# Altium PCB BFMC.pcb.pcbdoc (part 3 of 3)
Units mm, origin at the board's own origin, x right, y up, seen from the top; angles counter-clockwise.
Board outline 121.38 x 89.66 mm, 2 copper layers (Top Layer, Bottom Layer); 106 components, 51 nets, 277 pads, 97 vias.
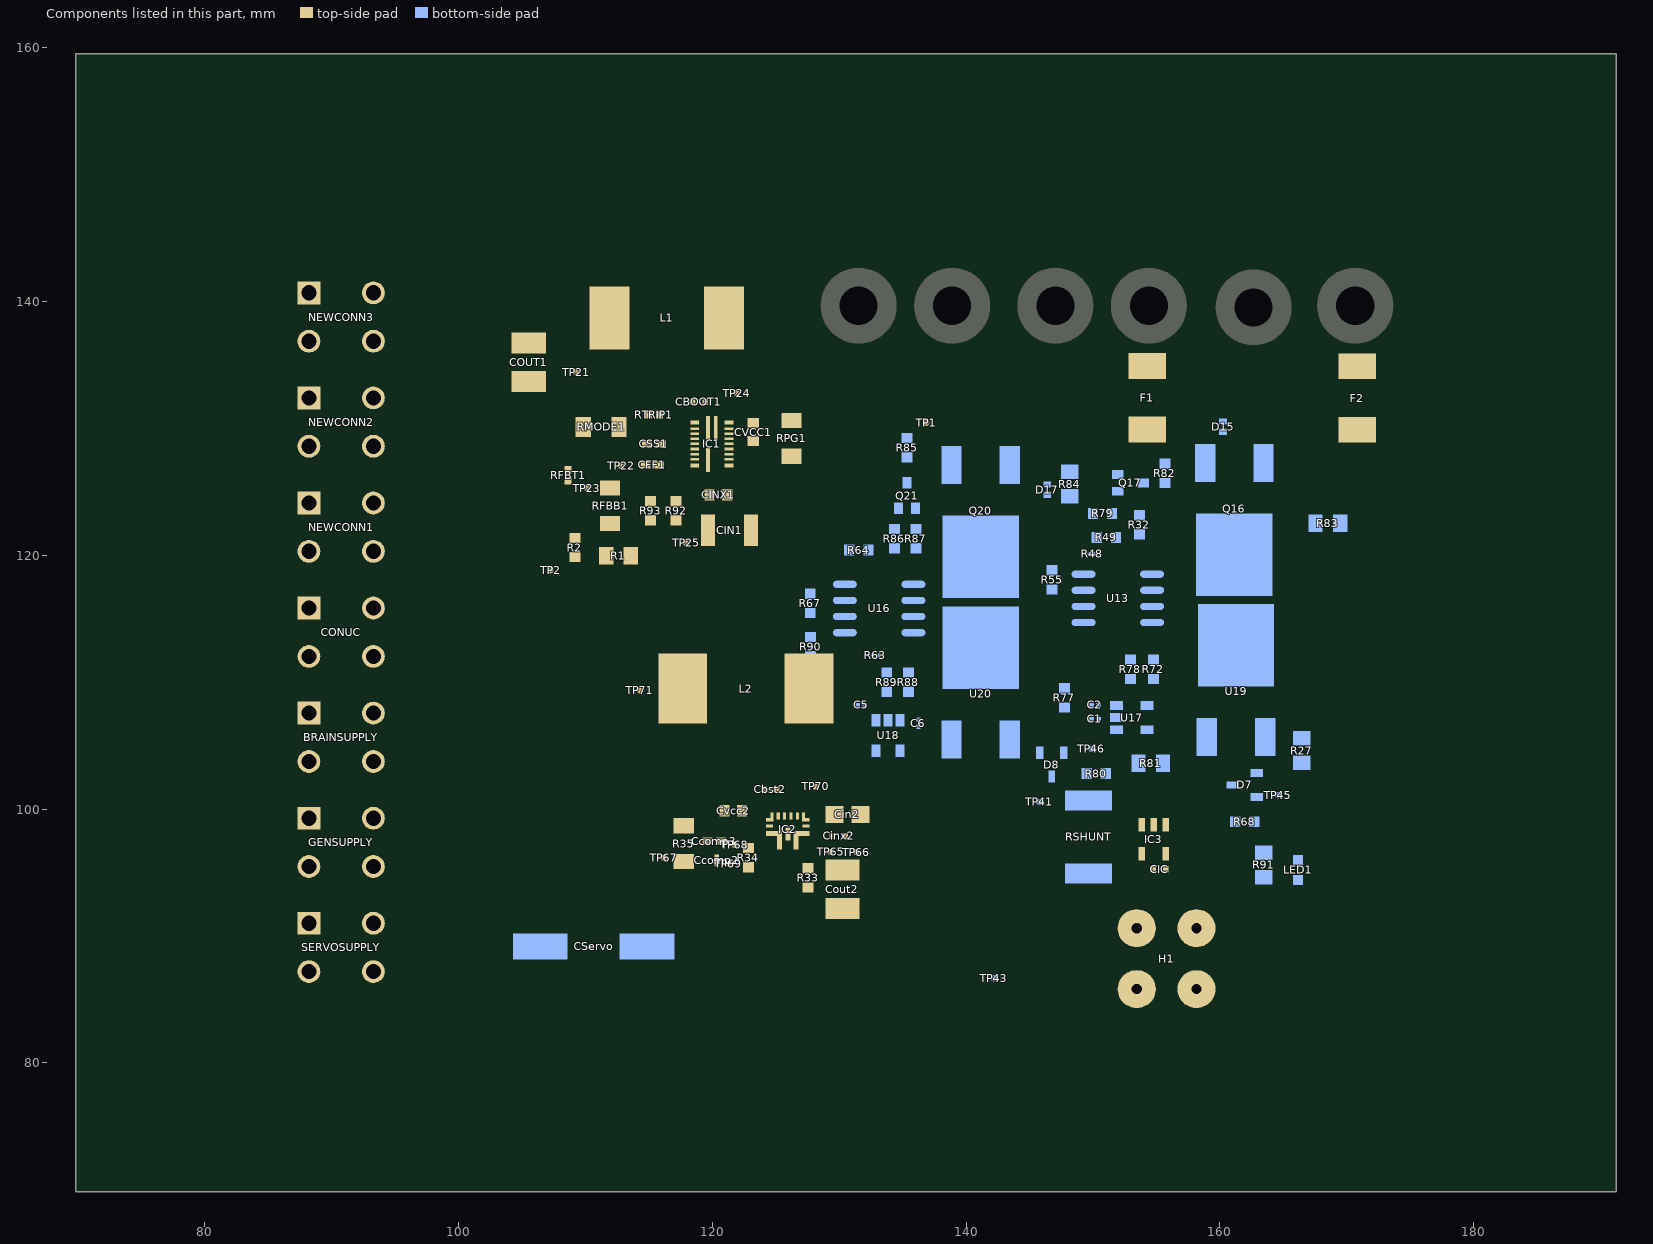
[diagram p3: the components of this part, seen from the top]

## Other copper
Top Layer:
  region net ISHUNT: 156.565,98.494 156.565,98.994 cw(c156.565,102.101) 155.995,99.046 155.995,98.441 cw(c156.565,95.386)
  region net UBATT: 152.813,99.002 152.813,98.502 cw(c152.813,97.395) 153.563,98.209 153.563,99.279 cw(c152.813,100.156)
  region net OUT_BATT: 152.813,96.724 152.813,96.224 cw(c152.813,90.864) 153.563,96.171 153.563,96.776 cw(c152.813,102.083)
  region net +5V: 155.47,95.256 155.97,95.256 cw(c165.333,95.256) 155.995,95.939 155.463,95.939 cw(c122.273,95.256)
  region net ADC1: 110.068,119.684 110.068,119.984 cw(c110.068,120.546) 109.618,120.209 109.618,119.459 cw(c110.068,119.121)
  region net ADC1: 108.304,119.984 108.304,119.684 cw(c108.304,119.121) 108.754,119.459 108.754,120.209 cw(c108.304,120.546)
  region net ADC1: 107.614,118.952 107.402,119.164 107.351,119.114 107.334,119.1 107.316,119.087 107.297,119.078 107.275,119.071 107.252,119.067 107.517,118.802 107.52,118.825 107.527,118.847 107.537,118.866 107.55,118.884 107.564,118.902
  region net VOUT1: 126.458,96.593 126.758,96.593 cw(c127.322,96.593) 126.808,96.825 126.408,96.825 cw(c125.895,96.593)
  region: 125.181,96.444 125.435,96.444 cw(c128.158,96.444) 125.462,96.825 125.155,96.825 cw(c122.459,96.444)
  region net VOUT1: 128.024,97.948 128.024,98.202 cw(c128.024,100.715) 127.658,98.228 127.658,97.921 cw(c128.024,95.434)
  region net SW_1: 126.108,98.775 125.808,98.775 cw(c124.805,98.775) 125.777,98.525 126.14,98.525 cw(c127.112,98.775)
  region: 124.162,98.202 124.162,97.948 cw(c124.162,97.761) 124.258,97.921 124.258,98.228 cw(c124.162,98.388)
  region: 125.458,98.656 125.204,98.656 cw(c124.728,98.656) 125.014,98.275 125.485,98.275 cw(c128.181,98.656)
  region net $3N2936: 120.97,95.55 120.97,95.85 cw(c120.97,98.827) 120.52,95.885 120.52,95.516 cw(c120.97,92.574)
  region net COMP: 121.899,96.822 122.111,97.034 122.08,97.066 122.066,97.083 122.053,97.101 122.041,97.12 122.032,97.139 122.026,97.16 122.023,97.181 121.758,96.916 121.78,96.913 121.801,96.906 121.819,96.897 121.835,96.885 121.851,96.871
  region net COMP: 121.636,97.509 121.424,97.297 121.476,97.247 121.49,97.231 121.503,97.214 121.513,97.195 121.52,97.174 121.524,97.15 121.789,97.415 121.766,97.418 121.745,97.425 121.725,97.435 121.706,97.447 121.687,97.461 121.653,97.493
  region net $3N2936: 121.57,95.541 121.57,95.841 121.535,95.842 121.517,95.844 121.499,95.848 121.481,95.853 121.465,95.859 121.45,95.868 121.436,95.878 121.436,95.503 121.45,95.513 121.465,95.522 121.481,95.528 121.499,95.533 121.517,95.537 121.535,95.539
  region net $3N2936: 120.93,95.85 120.93,95.55 120.977,95.549 121,95.546 121.023,95.542 121.046,95.536 121.067,95.527 121.087,95.517 121.105,95.503 121.105,95.878 121.085,95.863 121.065,95.854 121.045,95.848 121.024,95.846 121.003,95.847
  region net FB: 115.673,126.467 115.973,126.467 cw(c116.391,126.467) 116.198,126.838 115.448,126.838 cw(c115.254,126.467)
  region net FB: 116.518,127.008 116.518,127.208 cw(c116.518,127.583) 116.218,127.358 116.218,126.858 cw(c116.518,126.633)
  region net SS_REFIN: 116.645,128.659 116.645,128.859 cw(c116.645,129.234) 116.345,129.009 116.345,128.509 cw(c116.645,128.284)
  region net BOOT: 118.022,130.609 118.022,130.309 ccw(c118.022,130.859) 118.276,130.371 118.276,130.547 ccw(c118.022,130.058)
  region: 117.976,130.059 117.976,129.859 cw(c117.976,-124.034) 118.276,129.858 118.276,129.859 118.276,130.059 118.276,130.058 ccw(c117.976,-123.834)
  region net TRIP: 117.976,129.659 117.976,129.459 cw(c117.976,-124.434) 118.276,129.458 118.276,129.459 118.276,129.659 118.276,129.658 ccw(c117.976,-124.234)
  region net MODE: 117.976,129.259 117.976,129.059 cw(c117.976,-124.834) 118.276,129.058 118.276,129.059 118.276,129.259 118.276,129.258 ccw(c117.976,-124.634)
  region net SS_REFIN: 117.976,128.859 117.976,128.659 ccw(c117.976,129.766) 118.276,128.7 118.276,128.817 ccw(c117.976,127.751)
  region: 117.976,128.459 117.976,128.259 ccw(c117.976,129.366) 118.276,128.3 118.276,128.417 ccw(c117.976,127.351)
  region net FB: 117.976,128.059 117.976,127.859 cw(c117.976,-126.034) 118.276,127.858 118.276,127.859 118.276,128.059 118.276,128.058 ccw(c117.976,-125.834)
  region net EN: 117.976,127.659 117.976,127.459 cw(c117.976,-126.434) 118.276,127.458 118.276,127.459 118.276,127.659 118.276,127.658 ccw(c117.976,-126.234)
  region net PGOOD: 118.198,127.209 118.198,126.909 ccw(c118.198,126.989) 118.276,126.971 118.276,127.147 ccw(c118.198,127.129)
  region net VCC: 122.126,130.309 122.126,130.609 ccw(c122.126,128.947) 121.676,130.547 121.676,130.371 ccw(c122.126,131.97)
  region: 121.176,129.559 121.476,129.559 cw(c122.914,129.559) 121.508,129.859 121.145,129.859 cw(c119.738,129.559)
  region: 121.176,129.159 121.476,129.159 cw(c122.914,129.159) 121.508,129.459 121.145,129.459 cw(c119.738,129.159)
  region: 121.476,129.959 121.176,129.959 cw(c120.851,129.959) 120.976,129.659 121.676,129.659 cw(c121.801,129.959)
  region: 121.176,128.759 121.476,128.759 cw(c122.914,128.759) 121.508,129.059 121.145,129.059 cw(c119.738,128.759)
  region: 121.476,129.559 121.176,129.559 cw(c120.851,129.559) 120.976,129.259 121.676,129.259 cw(c121.801,129.559)
  region: 121.176,128.359 121.476,128.359 cw(c122.914,128.359) 121.508,128.659 121.145,128.659 cw(c119.738,128.359)
  region: 121.476,129.159 121.176,129.159 cw(c120.851,129.159) 120.976,128.859 121.676,128.859 cw(c121.801,129.159)
  region: 121.476,128.759 121.176,128.759 cw(c120.851,128.759) 120.976,128.459 121.676,128.459 cw(c121.801,128.759)
  region: 121.176,127.959 121.476,127.959 cw(c122.914,127.959) 121.508,128.259 121.145,128.259 cw(c119.738,127.959)
  region: 121.176,127.559 121.476,127.559 cw(c122.914,127.559) 121.508,127.859 121.145,127.859 cw(c119.738,127.559)
  region: 121.476,128.359 121.176,128.359 cw(c120.851,128.359) 120.976,128.059 121.676,128.059 cw(c121.801,128.359)
  region: 121.176,127.059 121.476,127.059 cw(c124.021,127.059) 121.508,127.459 121.145,127.459 cw(c118.632,127.059)
  region: 121.476,127.959 121.176,127.959 cw(c120.851,127.959) 120.976,127.659 121.676,127.659 cw(c121.801,127.959)
  region: 121.476,127.559 121.176,127.559 cw(c120.77,127.559) 120.976,127.209 121.676,127.209 cw(c121.883,127.559)
  region: 122.057,126.932 122.057,127.186 cw(c122.057,130.522) 121.676,127.207 121.676,126.91 cw(c122.057,123.596)
  region net SW: 120.403,131.34 120.149,131.34 cw(c116.813,131.34) 120.128,130.959 120.425,130.959 cw(c123.739,131.34)
  region net FB: 109.851,125.446 109.851,125.146 109.87,125.144 109.886,125.14 109.901,125.133 109.915,125.124 109.928,125.114 109.969,125.077 109.969,125.452 109.954,125.441 109.941,125.436 109.928,125.434 109.915,125.435 109.887,125.442 109.871,125.444
  region net FB: 110.475,125.146 110.475,125.446 110.46,125.445 110.446,125.444 110.433,125.441 110.41,125.436 110.379,125.428 110.37,125.426 110.361,125.426 110.351,125.426 110.342,125.428 110.332,125.431 110.322,125.436 110.311,125.443 110.3,125.452 110.3,125.077 110.316,125.09 110.336,125.102 110.359,125.114 110.382,125.124 110.407,125.133 110.431,125.14 110.454,125.144
  region net VBATT1: 152.046,87.564 151.693,87.21 151.783,87.115 151.847,87.041 151.896,86.976 151.942,86.91 151.974,86.856 152.003,86.801 152.022,86.76 152.038,86.717 152.051,86.674 152.062,86.631 152.067,86.602 152.071,86.573 152.073,86.543 152.073,86.514 152.072,86.484 152.069,86.454 152.064,86.424 152.058,86.394 152.05,86.363 152.039,86.333 152.923,87.217 152.893,87.206 152.862,87.198 152.832,87.192 152.802,87.187 152.772,87.184 152.743,87.183 152.713,87.183 152.683,87.186 152.654,87.189 152.611,87.197 152.567,87.209 152.525,87.223 152.483,87.24 152.441,87.26 152.386,87.289 152.332,87.323 152.267,87.369 152.19,87.43 152.105,87.507
  region net OUT_BATT2: 158.545,93.256 157.745,93.256 157.743,93.161 157.732,93.037 157.713,92.908 157.687,92.776 157.653,92.642 157.612,92.509 157.564,92.379 157.509,92.251 157.448,92.13 157.395,92.037 157.338,91.95 157.293,91.888 157.246,91.831 157.196,91.778 157.145,91.729 159.145,91.729 159.094,91.778 159.045,91.831 158.998,91.888 158.938,91.971 158.882,92.06 158.83,92.153 158.77,92.276 158.717,92.404 158.67,92.536 158.631,92.669 158.598,92.802 158.573,92.934 158.556,93.062 158.547,93.185
  region net EN: 116.338,124.376 116.338,124.122 cw(c116.338,123.646) 116.719,123.932 116.719,124.567 cw(c116.338,124.852)
  region net EN: 115.964,124.122 115.964,124.376 cw(c115.964,124.852) 115.583,124.567 115.583,123.932 cw(c115.964,123.646)
  region net VOUT1: 132.177,94.692 132.177,95.692 cw(c132.177,96.36) 131.608,96.01 131.608,94.375 cw(c132.177,94.024)
  region net COMP: 121.458,97.325 121.458,97.625 cw(c121.458,99.687) 121.099,97.656 121.099,97.293 cw(c121.458,95.262)
  region net FB_1: 119.009,98.525 119.009,98.825 cw(c119.009,99.387) 118.559,99.05 118.559,98.3 cw(c119.009,97.962)
  region net FB_1: 126.376,94.071 126.376,93.571 cw(c126.376,88.212) 127.126,93.519 127.126,94.124 cw(c126.376,99.431)
  region net COMP: 122.005,97.078 122.005,96.778 cw(c122.005,96.271) 122.426,96.553 122.426,97.303 cw(c122.005,97.585)
  region net COMP: 123.029,97.712 122.775,97.712 cw(c122.299,97.712) 122.585,97.331 123.22,97.331 cw(c123.506,97.712)
  region net $3N2936: 121.976,95.571 121.976,95.271 cw(c121.976,94.709) 122.426,95.046 122.426,95.796 cw(c121.976,96.134)
  region net MODE: 113.551,129.802 113.551,130.002 cw(c113.551,130.377) 113.251,130.152 113.251,129.652 cw(c113.551,129.427)
  region net VCC: 124.152,130.246 124.152,130.546 cw(c124.152,131.108) 123.702,130.771 123.702,130.021 cw(c124.152,129.683)
  region net VCC: 122.352,130.609 122.352,130.309 cw(c122.352,129.746) 122.802,130.084 122.802,130.796 cw(c122.352,131.243)
  region net FB: 109.351,125.646 109.351,125.946 cw(c109.351,126.508) 108.921,126.146 108.921,125.58 cw(c109.351,124.204)
  region net FB: 113.202,125.146 113.202,125.446 cw(c113.202,126.008) 112.752,125.671 112.752,124.921 cw(c113.202,124.583)
  region net FB: 110.701,125.446 110.701,125.146 cw(c110.701,124.583) 111.151,124.921 111.151,125.671 cw(c110.701,126.008)
  region net VCC: 125.001,130.546 125.001,130.246 cw(c125.001,129.683) 125.451,130.021 125.451,130.771 cw(c125.001,131.108)
  region net PGOOD: 126.101,126.746 126.401,126.746 cw(c126.964,126.746) 126.626,127.196 125.876,127.196 cw(c125.539,126.746)
  region net SW_1: 123.383,101.725 123.383,101.425 cw(c123.383,100.362) 123.833,101.325 123.833,101.825 cw(c123.383,102.787)
  region net BOOT: 118.027,132.246 118.027,131.946 cw(c118.027,131.697) 118.226,131.846 118.226,132.346 cw(c118.027,132.494)
  region net OUT_BATT: 114.598,119.811 114.598,120.111 cw(c114.598,120.673) 114.148,120.336 114.148,119.586 cw(c114.598,119.248)
  region net ADC1: 110.633,119.984 110.633,119.684 cw(c110.633,119.121) 111.083,119.459 111.083,120.209 cw(c110.633,120.546)
  region net ADC1: 94.537,115.581 94.537,116.081 94.493,116.083 94.453,116.087 94.427,116.091 94.403,116.096 94.38,116.102 94.358,116.109 94.337,116.118 94.316,116.127 94.297,116.137 94.269,116.154 94.242,116.172 94.216,116.192 94.183,116.221 94.135,116.27 93.999,116.417 93.94,116.476 93.907,116.506 93.907,115.156 93.97,115.216 94.095,115.349 94.167,115.425 94.2,115.456 94.225,115.477 94.251,115.497 94.278,115.514 94.306,115.531 94.326,115.54 94.347,115.549 94.369,115.557 94.391,115.563 94.415,115.569 94.44,115.574 94.479,115.579 94.522,115.581
  region: 117.24,128.167 117.098,128.308 117.08,128.292 117.059,128.279 117.037,128.269 117.013,128.261 116.988,128.255 116.963,128.251 116.913,128.246 117.178,127.981 117.183,128.031 117.187,128.056 117.193,128.081 117.201,128.105 117.211,128.127 117.224,128.148
  region: 117.136,130.644 117.277,130.785 117.268,130.797 117.262,130.81 117.259,130.825 117.258,130.841 117.259,130.858 117.262,130.876 117.271,130.914 117.295,130.991 117.299,131.01 117.303,131.028 117.305,131.044 117.305,131.06 117.04,130.795 117.058,130.789 117.072,130.775 117.084,130.756 117.094,130.733 117.112,130.683 117.123,130.661
  region net PGOOD: 118.094,126.436 117.794,126.436 117.797,126.375 117.797,126.353 117.797,126.342 117.796,126.331 117.794,126.321 117.792,126.311 117.788,126.301 117.784,126.291 117.779,126.281 117.772,126.271 117.764,126.261 118.139,126.261 118.125,126.279 118.115,126.299 118.107,126.32 118.101,126.343 118.098,126.366 118.095,126.413
  region net PGOOD: 125.998,126.23 125.786,126.442 125.735,126.392 125.718,126.378 125.7,126.365 125.681,126.356 125.659,126.349 125.636,126.345 125.901,126.08 125.904,126.104 125.911,126.125 125.921,126.144 125.934,126.162 125.948,126.18
  region net FB: 109.851,125.446 109.851,125.146 109.87,125.144 109.886,125.14 109.901,125.133 109.915,125.124 109.928,125.114 109.969,125.077 109.969,125.452 109.954,125.441 109.941,125.436 109.928,125.434 109.915,125.435 109.887,125.442 109.871,125.444
  region net FB: 110.475,125.146 110.475,125.446 110.46,125.445 110.446,125.444 110.433,125.441 110.41,125.436 110.379,125.428 110.37,125.426 110.361,125.426 110.351,125.426 110.342,125.428 110.332,125.431 110.322,125.436 110.311,125.443 110.3,125.452 110.3,125.077 110.316,125.09 110.336,125.102 110.359,125.114 110.382,125.124 110.407,125.133 110.431,125.14 110.454,125.144
  region net COMP: 121.899,96.822 122.111,97.034 122.08,97.066 122.066,97.083 122.053,97.101 122.041,97.12 122.032,97.139 122.026,97.16 122.023,97.181 121.758,96.916 121.78,96.913 121.801,96.906 121.819,96.897 121.835,96.885 121.851,96.871
  region net COMP: 121.636,97.509 121.424,97.297 121.476,97.247 121.49,97.231 121.503,97.214 121.513,97.195 121.52,97.174 121.524,97.15 121.789,97.415 121.766,97.418 121.745,97.425 121.725,97.435 121.706,97.447 121.687,97.461 121.653,97.493
  region net ADC1: 110.068,119.684 110.068,119.984 cw(c110.068,120.546) 109.618,120.209 109.618,119.459 cw(c110.068,119.121)
  region net ADC1: 108.304,119.984 108.304,119.684 cw(c108.304,119.121) 108.754,119.459 108.754,120.209 cw(c108.304,120.546)
  region net VOUT1: 132.562,93.164 133.562,93.164 133.062,93.807 132.531,95.546
Bottom Layer:
  region net VBATT1: 150.901,107.246 150.901,106.946 cw(c150.877,106.884) 150.931,106.922 150.931,107.266 cw(c150.838,107.369)
  region net VBATT1: 150.931,107.266 150.931,107.471 cw(c150.838,107.369)
  region net VBATT1: 150.931,106.922 cw(c150.877,106.884) 150.931,106.846
  region: 150.004,107.639 149.75,107.639 cw(c147.027,107.639) 149.723,107.258 150.031,107.258 cw(c152.727,107.639)
  region net VBATT1: 151.06,106.946 151.06,107.246 ccw(c151.06,105.584) 150.61,107.184 150.61,107.008 ccw(c151.06,108.607)
  region: 149.75,107.653 150.004,107.653 cw(c151.301,107.653) 150.061,108.034 149.693,108.034 cw(c148.453,107.653)
  region net +VCC2: 151.06,108.046 151.06,108.346 ccw(c151.06,106.684) 150.61,108.284 150.61,108.108 ccw(c151.06,109.707)
  region net $1N1798: 163.766,102.596 163.766,103.096 cw(c163.766,104.508) 163.376,103.151 163.376,102.541 cw(c163.766,101.183)
  region net $1N1798: 163.139,103.432 162.639,103.432 cw(c161.861,103.432) 162.586,103.151 163.191,103.151 cw(c163.916,103.432)
  region net UBATT: 159.777,102.146 159.777,101.646 ccw(c159.777,104.414) 160.527,101.749 160.527,102.042 ccw(c159.777,99.377)
  region net $1N1788: 145.951,104.974 145.651,104.974 cw(c145.591,104.974) 145.62,104.921 145.983,104.921 cw(c146.012,104.974)
  region net $1N1788: 146.102,104.974 145.502,104.974 ccw(c145.575,104.974) 145.626,104.921 145.977,104.921 ccw(c146.028,104.974)
  region net $1N2516: 151.685,124.38 152.185,124.38 cw(c153.097,124.38) 152.238,124.685 151.633,124.685 cw(c150.774,124.38)
  region net $1N2412: 155.167,125.446 155.167,125.946 cw(c155.167,131.305) 154.417,125.998 154.417,125.393 cw(c155.167,120.086)
  region net $1N20962: 152.751,121.146 152.751,121.646 cw(c152.751,124.472) 152.208,121.698 152.208,121.093 cw(c152.751,118.32)
  region net $1N20946: 150.043,120.514 150.343,120.514 cw(c150.906,120.514) 150.568,120.964 150.011,120.964 cw(c146.827,120.514)
  region net $1N2337: 159.19,129.971 159.19,129.471 ccw(c159.19,132.239) 159.94,129.574 159.94,129.867 ccw(c159.19,127.202)
  region net $1N20674: 146.501,116.149 147.001,116.149 cw(c152.361,116.149) 147.054,116.899 146.449,116.899 cw(c141.142,116.149)
  region net $1N20674: 147.96,116.981 147.96,117.481 cw(c147.96,118.844) 147.21,117.706 147.21,116.899 cw(c147.96,113.494)
  region net VBATT2: 132.176,108.808 131.876,108.808 cw(c128.899,108.808) 131.842,108.358 132.21,108.358 cw(c135.152,108.808)
  region net VBATT2: 132.66,108.046 132.66,108.346 cw(c132.66,116.788) 132.21,108.358 132.21,108.034 cw(c132.66,99.603)
  region net +VCC3: 135.625,107.146 135.625,106.846 cw(c135.625,71.97) 136.075,106.843 136.075,107.211 cw(c135.625,108.724)
  region net +VCC3: 136.387,107.661 136.087,107.661 ccw(c137.749,107.661) 136.15,107.211 136.325,107.211 ccw(c134.726,107.661)
  region net $1N27792: 140.137,126.86 140.137,127.36 cw(c140.137,127.861) 139.652,127.735 139.652,126.485 cw(c140.137,126.358)
  region net $1N27792: 139.102,129.36 138.602,129.36 cw(c137.665,129.36) 138.227,128.61 139.477,128.61 cw(c140.04,129.36)
  region net $1N27799: 135.801,122.48 136.301,122.48 cw(c141.661,122.48) 136.354,123.23 135.749,123.23 cw(c130.442,122.48)
  region net $1N27793: 135.601,126.912 135.101,126.912 cw(c129.742,126.912) 135.049,126.162 135.654,126.162 cw(c140.961,126.912)
  region net $1N27811: 133.458,120.146 133.458,120.646 cw(c133.458,126.005) 132.708,120.698 132.708,120.093 cw(c133.458,114.786)
  region net $1N27807: 131.407,119.433 131.732,119.816 cw(c136.071,124.154) 131.201,120.421 130.802,119.964 cw(c127.068,115.094)
  region net $1N27822: 128.37,115.192 128.37,115.692 cw(c128.37,116.151) 128.156,115.745 128.156,115.14 cw(c128.37,114.733)
  region net $1N27822: 127.501,114.289 128.001,114.289 cw(c129.893,114.289) 128.156,115.039 127.292,115.039 cw(c126.051,114.289)
  region net VBATT1: 147.501,106.851 148.001,106.851 cw(c149.638,106.851) 148.183,107.601 147.319,107.601 cw(c145.865,106.851)
  region net $1N20674: 148.001,110.606 147.501,110.606 cw(c146.097,110.606) 147.319,109.914 148.183,109.914 cw(c149.406,110.606)
  region net +VCC2: 152.701,109.246 153.201,109.246 cw(c154.26,109.246) 153.383,109.839 152.519,109.839 cw(c151.643,109.246)
  region net +VCC2: 151.985,110.432 151.985,109.932 cw(c151.985,108.345) 152.519,109.839 152.519,110.646 cw(c151.985,111.205)
  region net $1N21052: 154.133,111.499 154.133,111.999 cw(c154.133,117.359) 153.383,112.052 153.383,111.446 cw(c154.133,106.139)
  region net $1N21052: 153.569,111.999 153.569,111.499 cw(c153.569,109.587) 154.319,111.346 154.319,112.152 cw(c153.569,113.911)
  region net $1N21052: 155.714,112.358 155.331,112.683 cw(c150.993,117.021) 154.727,112.152 155.183,111.753 cw(c160.053,108.019)
  region net $1N2516: 151.755,123.949 151.255,123.949 cw(c151.018,123.949) 151.102,123.728 151.908,123.728 cw(c151.991,123.949)
  region net $1N2516: 152.658,123.046 152.658,123.546 cw(c152.658,125.182) 151.908,123.728 151.908,122.864 cw(c152.658,121.409)
  region net UBATT: 160.948,97.814 161.448,97.814 cw(c163.36,97.814) 161.601,98.564 160.795,98.564 cw(c159.036,97.814)
  region net UBATT: 160.045,99.246 160.045,98.746 cw(c160.045,93.386) 160.795,98.693 160.795,99.298 cw(c160.045,104.605)
  region net $1N1798: 163.858,98.746 163.858,99.246 cw(c163.858,104.605) 163.108,99.298 163.108,98.693 cw(c163.858,93.386)
  region net $1N1788: 151.838,102.546 151.838,103.046 cw(c151.838,104.828) 151.408,103.098 151.408,102.493 cw(c151.838,100.763)
  region net $1N1788: 151.155,103.669 150.855,103.669 cw(c150.309,103.669) 150.63,103.228 151.38,103.228 cw(c151.701,103.669)
  region net $1N1798: 164.563,106.068 164.563,105.268 cw(c164.563,96.693) 165.763,105.184 165.763,105.903 ccw(c164.563,101.638)
  region net $1N1788: 152.638,103.846 152.638,103.346 cw(c152.638,102.965) 153.019,102.971 153.019,104.221 cw(c152.638,104.226)
  region net $1N2412: 154.486,125.946 154.486,125.446 cw(c154.486,123.655) 155.236,125.281 155.236,126.088 cw(c154.486,127.999)
  region net OUT_BATT1: 168.959,120.312 169.959,120.312 ccw(c164.421,120.312) 169.751,121.812 169.166,121.812 ccw(c174.496,120.312)
  region net OUT_BATT1: 169.918,124.389 169.118,124.389 cw(c160.542,124.389) 169.033,123.189 170.002,123.189 cw(c178.493,124.389)
  region net $1N2337: 167.835,123.665 167.335,123.665 cw(c166.843,123.665) 166.97,123.189 167.888,123.189 cw(c170.007,123.665)
  region net $1N27792: 146.713,124.956 146.713,124.456 cw(c146.713,123.518) 147.463,124.081 147.463,125.196 cw(c146.713,126.247)
  region net $1N27792: 135.598,129.875 135.098,129.875 cw(c134.838,129.875) 134.916,129.626 135.78,129.626 cw(c135.859,129.875)
  region net $1N27793: 135.101,126.563 135.601,126.563 cw(c137.262,126.563) 135.78,127.313 134.916,127.313 cw(c133.489,126.563)
  region net $1N27799: 134.869,122.299 134.869,121.799 cw(c134.869,116.439) 135.619,121.746 135.619,122.352 cw(c134.869,127.659)
  region net $1N27799: 136.301,123.202 135.801,123.202 cw(c134.165,123.202) 135.619,122.452 136.483,122.452 cw(c137.938,123.202)
  region net $1N32332: 134.942,109.964 134.701,109.78 cw(c133.906,108.985) 135.019,109.144 135.579,109.646 cw(c135.738,110.759)
  region net +VCC3: 136.237,110.667 136.237,110.967 cw(c136.237,111.397) 135.883,111.152 135.883,110.442 cw(c136.237,110.276)
  region net +VCC3: 135.701,111.809 135.201,111.809 cw(c133.927,111.809) 135.019,111.152 135.883,111.152 cw(c136.976,111.809)
  region net $1N32332: 134.454,110.028 134.502,110.404 cw(c137.105,113.008) 134.183,110.767 133.818,110.346 cw(c133.659,109.232)
  region net $1N27822: 128.001,114.702 127.501,114.702 cw(c122.142,114.702) 127.449,113.952 128.054,113.952 cw(c133.361,114.702)
  region net VBATT2: 127.351,110.439 128.151,110.439 ccw(c123.721,110.439) 127.986,111.639 127.517,111.639 ccw(c131.781,110.439)
  region net VBATT2: 128.633,111.892 128.633,112.192 cw(c128.633,112.755) 128.183,112.417 128.183,111.667 cw(c128.633,111.33)
  region net $1N1788: 150.036,104.426 150.248,104.638 150.237,104.648 150.226,104.657 150.215,104.665 150.195,104.677 150.168,104.692 150.16,104.698 150.153,104.704 150.146,104.71 150.141,104.718 150.136,104.727 150.132,104.738 150.13,104.751 150.128,104.765 149.863,104.5 149.884,104.498 149.907,104.492 149.931,104.485 149.955,104.476 149.979,104.465 150.001,104.453 150.02,104.44
  region net $1N1788: 149.767,105.119 149.555,104.907 149.569,104.891 149.582,104.872 149.594,104.85 149.605,104.826 149.614,104.802 149.621,104.778 149.626,104.755 149.629,104.734 149.894,104.999 149.879,105.001 149.867,105.003 149.856,105.007 149.847,105.012 149.839,105.017 149.833,105.024 149.827,105.031 149.821,105.039 149.806,105.066 149.794,105.086 149.786,105.097 149.777,105.108
  region net VBATT1: 150.901,107.246 150.901,106.946 cw(c150.901,105.883) 151.351,106.846 151.351,107.471 cw(c150.901,107.808)
  region net +VCC2: 150.901,108.346 150.901,108.046 cw(c150.901,107.483) 151.351,107.821 151.351,108.496 cw(c150.901,109.096)
  region net +VCC2: 152.882,108.822 152.378,109.026 cw(c148.039,113.365) 151.773,108.496 152.351,108.217 cw(c157.221,104.484)
  region net +VCC3: 135.601,106.846 135.601,107.146 cw(c135.601,107.708) 135.151,107.371 135.151,106.621 cw(c135.601,106.283)
  region net UBATT: 162.013,96.846 162.013,96.346 cw(c162.013,90.986) 162.763,96.293 162.763,96.898 cw(c162.013,102.205)
  region net $1N40141: 164.89,94.146 164.89,94.646 cw(c164.89,95.584) 164.14,95.021 164.14,94.093 cw(c164.89,88.786)
  region net $1N40141: 164.998,94.646 164.998,94.146 cw(c164.998,92.196) 165.748,93.996 165.748,94.796 cw(c164.998,96.596)
  region net $1N20931: 149.502,115.728 149.002,115.728 148.999,115.485 148.991,115.388 148.983,115.326 148.974,115.281 148.964,115.239 148.951,115.199 148.941,115.174 148.93,115.15 148.918,115.127 148.904,115.106 148.889,115.086 148.872,115.067 148.854,115.05 148.834,115.035 148.813,115.021 148.789,115.009 148.764,114.999 148.738,114.991 148.709,114.984 148.678,114.98 148.645,114.978 148.627,114.978 149.877,114.978 149.843,114.979 149.811,114.982 149.782,114.987 149.754,114.994 149.728,115.004 149.704,115.015 149.681,115.028 149.661,115.042 149.642,115.058 149.624,115.076 149.608,115.095 149.594,115.116 149.581,115.138 149.569,115.162 149.559,115.186 149.549,115.212 149.537,115.253 149.528,115.296 149.518,115.356 149.509,115.436 149.504,115.57
  region net $1N20931: 149.002,114.924 149.502,114.924 149.506,115.166 149.514,115.264 149.522,115.326 149.531,115.37 149.541,115.412 149.554,115.452 149.564,115.478 149.575,115.502 149.587,115.524 149.601,115.546 149.616,115.566 149.633,115.584 149.651,115.601 149.671,115.617 149.692,115.63 149.715,115.642 149.74,115.652 149.767,115.661 149.796,115.667 149.827,115.671 149.86,115.673 149.877,115.674 148.627,115.674 148.662,115.673 148.693,115.669 148.723,115.664 148.751,115.657 148.777,115.648 148.801,115.637 148.824,115.624 148.844,115.609 148.863,115.593 148.881,115.575 148.896,115.556 148.911,115.535 148.924,115.513 148.936,115.49 148.946,115.465 148.956,115.439 148.968,115.399 148.977,115.356 148.987,115.295 148.995,115.215 149.001,115.081
  region net $1N20931: 150.604,115.811 150.604,116.111 150.568,116.117 149.921,116.246 149.909,116.248 149.909,115.674 149.946,115.68 150.592,115.809
  region net $1N20674: 147.705,117.481 147.705,116.981 147.722,116.981 147.74,116.983 147.779,116.991 147.822,117.003 147.938,117.044 148.106,117.105 148.152,117.118 148.195,117.127 148.215,117.13 148.235,117.132 148.253,117.132 148.271,117.131 148.287,117.128 148.302,117.123 148.316,117.117 148.329,117.108 148.339,117.097 148.349,117.084 148.349,117.377 148.339,117.364 148.329,117.353 148.316,117.345 148.302,117.338 148.287,117.333 148.271,117.33 148.253,117.329 148.235,117.329 148.215,117.331 148.174,117.338 148.129,117.349 148.059,117.372 147.867,117.443 147.8,117.464 147.759,117.474 147.74,117.478 147.722,117.48
  region net +VCC2: 153.103,114.941 153.103,114.441 153.993,114.404 153.993,114.978
  region net $1N20962: 153.46,116.111 153.46,115.811 153.486,115.812 153.511,115.814 153.545,115.819 153.617,115.833 153.635,115.836 153.653,115.838 153.662,115.838 153.671,115.838 153.679,115.837 153.688,115.835 153.696,115.833 153.705,115.83 153.713,115.827 153.721,115.823 153.73,115.818 153.738,115.812 153.746,115.805 153.754,115.798 153.763,115.789 153.771,115.779 153.771,116.142 153.754,116.124 153.738,116.109 153.721,116.098 153.705,116.091 153.688,116.086 153.671,116.084 153.653,116.084 153.635,116.085 153.598,116.092 153.534,116.104 153.486,116.11
  region net $1N21052: 156.198,116.981 156.198,117.481 155.307,117.518 155.307,116.944
  region net $1N20946: 153.299,118.651 153.299,118.351 153.339,118.352 153.377,118.356 153.413,118.363 153.479,118.378 153.552,118.397 153.579,118.402 153.606,118.405 153.619,118.405 153.631,118.404 153.644,118.403 153.657,118.4 153.669,118.397 153.682,118.392 153.694,118.386 153.707,118.379 153.72,118.37 153.732,118.36 153.745,118.348 153.758,118.334 153.771,118.319 153.771,118.682 153.758,118.667 153.745,118.653 153.732,118.642 153.72,118.631 153.707,118.623 153.694,118.615 153.682,118.609 153.669,118.604 153.657,118.601 153.644,118.598 153.631,118.597 153.619,118.596 153.606,118.597 153.579,118.599 153.552,118.604 153.463,118.627 153.413,118.639 153.377,118.645 153.339,118.649
  region net $1N27802: 130.702,114.928 130.202,114.928 130.199,114.685 130.191,114.588 130.183,114.526 130.174,114.481 130.164,114.439 130.151,114.399 130.141,114.374 130.13,114.35 130.118,114.327 130.104,114.306 130.089,114.286 130.072,114.267 130.054,114.25 130.034,114.235 130.013,114.221 129.989,114.209 129.964,114.199 129.938,114.191 129.909,114.184 129.878,114.18 129.845,114.178 129.827,114.178 131.077,114.178 131.043,114.179 131.011,114.182 130.982,114.187 130.954,114.194 130.928,114.204 130.904,114.215 130.881,114.228 130.861,114.242 130.842,114.258 130.824,114.276 130.808,114.295 130.794,114.316 130.781,114.338 130.769,114.362 130.759,114.386 130.749,114.412 130.737,114.453 130.728,114.496 130.718,114.556 130.709,114.636 130.704,114.77
  region net $1N27802: 131.208,113.285 131.585,113.333 131.563,113.356 131.542,113.382 131.521,113.41 131.491,113.455 131.465,113.503 131.441,113.553 131.421,113.605 131.41,113.64 131.401,113.675 131.394,113.71 131.39,113.745 131.388,113.779 131.389,113.812 131.393,113.843 130.572,113.604 130.614,113.602 130.657,113.597 130.7,113.588 130.744,113.576 130.787,113.562 130.83,113.545 130.894,113.515 130.956,113.481 131.016,113.443 131.073,113.402 131.127,113.359 131.177,113.315
  region net $1N27802: 130.202,114.124 130.702,114.124 130.706,114.366 130.714,114.464 130.722,114.526 130.731,114.57 130.741,114.612 130.754,114.652 130.764,114.678 130.775,114.702 130.787,114.724 130.801,114.746 130.816,114.766 130.833,114.784 130.851,114.801 130.871,114.817 130.892,114.83 130.915,114.842 130.94,114.852 130.967,114.861 130.996,114.867 131.027,114.871 131.06,114.873 131.077,114.874 129.827,114.874 129.862,114.873 129.893,114.869 129.923,114.864 129.951,114.857 129.977,114.848 130.001,114.837 130.024,114.824 130.044,114.809 130.063,114.793 130.081,114.775 130.096,114.756 130.111,114.735 130.124,114.713 130.136,114.69 130.146,114.665 130.156,114.639 130.168,114.599 130.177,114.556 130.187,114.495 130.195,114.415 130.201,114.281
  region net $1N27822: 129.358,116.681 129.358,116.181 129.77,116.145 129.795,116.144 129.795,116.718 129.383,116.682
  region net +VCC3: 136.999,113.615 136.999,114.115 136.929,114.117 136.819,114.126 136.705,114.142 136.628,114.157 136.584,114.167 136.737,113.718 136.747,113.728 136.759,113.733 136.773,113.734 136.787,113.731 136.803,113.724 136.82,113.715 136.855,113.692 136.911,113.652 136.93,113.64 136.948,113.63 136.966,113.622 136.983,113.617
  region net $1N27811: 137.025,114.911 137.025,115.411 137.009,115.409 136.992,115.403 136.973,115.395 136.954,115.384 136.875,115.332 136.837,115.308 136.819,115.299 136.803,115.293 136.788,115.29 136.775,115.291 136.763,115.297 136.754,115.307 136.754,115.014 136.763,115.025 136.775,115.03 136.788,115.031 136.803,115.028 136.819,115.022 136.837,115.013 136.875,114.989 136.954,114.937 136.973,114.926 136.992,114.918 137.009,114.913
  region net $1N32332: 134.303,116.681 134.303,116.181 135.193,116.144 135.193,116.718
  region net $1N27807: 134.496,117.846 134.502,117.546 134.538,117.54 135.182,117.415 135.193,117.414 135.193,117.988 135.157,117.982
  region net $1N27807: 134.303,117.951 134.303,117.451 135.193,117.414 135.193,117.988
  region net OUT_BATT1: 161.06,85.311 161.06,86.311 160.947,86.314 160.832,86.324 160.698,86.342 160.544,86.371 160.372,86.414 160.182,86.471 159.958,86.552 159.721,86.651 159.475,86.769 159.228,86.903 159.015,87.034 158.975,87.061 158.975,84.561 159.184,84.692 159.428,84.828 159.671,84.948 159.906,85.049 160.13,85.133 160.337,85.198 160.51,85.242 160.664,85.274 160.798,85.294 160.914,85.305 161.028,85.31
  region net VBATT2: 150.8,91.011 150.8,90.211 150.895,90.208 151.019,90.197 151.148,90.178 151.28,90.152 151.414,90.118 151.547,90.077 151.678,90.029 151.805,89.974 151.927,89.913 152.019,89.86 152.106,89.803 152.168,89.758 152.225,89.711 152.279,89.662 152.327,89.611 152.327,91.611 152.279,91.56 152.225,91.51 152.168,91.463 152.085,91.404 151.996,91.347 151.903,91.295 151.78,91.235 151.652,91.182 151.52,91.135 151.387,91.096 151.254,91.063 151.122,91.038 150.994,91.021 150.871,91.012
  region net $1N20946: 150.795,119.946 150.795,120.246 cw(c150.795,128.688) 150.345,120.258 150.345,119.934 cw(c150.795,111.503)
  region net $1N20946: 150.343,120.708 150.043,120.708 cw(c85.228,120.708) 150.041,120.258 150.345,120.258 cw(c215.158,120.708)
  region net $1N20931: 149.56,119.696 149.86,119.696 ccw(c149.375,119.696) 149.798,119.934 149.622,119.934 ccw(c150.045,119.696)
  region net $1N27807: 133.243,112.708 132.943,112.708 ccw(c134.604,112.708) 133.005,112.258 133.181,112.258 ccw(c131.582,112.708)
  region net $1N27802: 132.342,112.576 132.14,112.353 cw(c130.773,110.986) 132.458,111.934 132.458,112.258 ccw(c132.057,112.291)
  region net $1N2516: 152.469,123.546 152.469,123.046 cw(c152.469,117.686) 153.219,122.993 153.219,123.442 ccw(c152.469,120.777)
  region net $1N20962: 152.998,121.892 152.998,121.392 cw(c152.998,121.156) 153.219,121.239 153.219,122.046 cw(c152.998,122.129)
  region net $1N20962: 154.533,121.492 154.533,121.792 cw(c154.533,122.355) 154.083,122.017 154.083,121.267 cw(c154.533,120.93)
  region net $1N27811: 133.169,120.646 133.169,120.146 cw(c133.169,77.538) 133.919,120.139 133.919,120.946 cw(c133.169,121.733)
  region net $1N27811: 133.95,119.712 134.45,119.712 cw(c134.889,119.712) 134.783,120.139 133.919,120.139 cw(c130.929,119.712)
  region net $1N27799: 135.533,121.799 135.533,122.299 cw(c135.533,124.211) 134.783,122.452 134.783,121.646 cw(c135.533,119.887)
  region net $1N1798: 165.565,105.268 165.565,106.068 cw(c165.565,107.568) 164.365,106.668 164.365,104.668 cw(c165.565,103.768)
  region net $1N1788: 145.151,105.564 145.151,106.164 cw(c145.151,107.289) 144.251,106.614 144.251,105.114 cw(c145.151,104.439)
  region net $1N2337: 160.038,126.86 160.038,127.36 cw(c160.038,127.768) 159.63,127.735 159.63,126.485 cw(c160.038,126.451)
  region net $1N2337: 157.28,127.36 157.28,126.86 cw(c157.28,125.922) 158.03,126.485 158.03,127.735 cw(c157.28,128.297)
  region net $1N2337: 159.102,129.458 158.602,129.458 cw(c157.761,129.458) 158.227,128.758 159.477,128.758 cw(c159.944,129.458)
  region net ISHUNT: 94.537,111.771 94.537,112.271 94.493,112.273 94.453,112.277 94.427,112.281 94.403,112.286 94.38,112.292 94.358,112.299 94.337,112.308 94.316,112.317 94.297,112.327 94.269,112.344 94.242,112.362 94.216,112.382 94.183,112.412 94.135,112.46 93.999,112.607 93.94,112.666 93.907,112.696 93.907,111.346 93.97,111.406 94.095,111.539 94.167,111.615 94.2,111.646 94.225,111.667 94.251,111.687 94.278,111.704 94.306,111.721 94.326,111.73 94.347,111.739 94.369,111.747 94.391,111.753 94.415,111.759 94.44,111.764 94.479,111.769 94.522,111.771
  region net UBATT: 149.401,99.435 149.901,99.435 cw(c150.342,99.435) 150.276,99.871 149.026,99.871 cw(c148.96,99.435)
  region net PGOOD: 118.292,125.946 118.292,126.246 118.22,126.246 118.198,126.248 118.177,126.252 118.156,126.259 118.136,126.269 118.117,126.283 118.117,125.908 118.136,125.922 118.156,125.932 118.177,125.939 118.198,125.943 118.22,125.945
  region net PGOOD: 125.311,126.246 125.311,125.946 125.382,125.945 125.405,125.943 125.426,125.939 125.447,125.932 125.467,125.922 125.486,125.908 125.486,126.283 125.467,126.269 125.447,126.259 125.426,126.252 125.405,126.248 125.382,126.246
  region net VBATT1: 150.611,106.331 150.311,106.331 150.311,106.26 150.309,106.237 150.305,106.216 150.298,106.195 150.288,106.175 150.274,106.156 150.649,106.156 150.635,106.175 150.625,106.195 150.618,106.216 150.614,106.237 150.612,106.26
  region net VBATT1: 150.311,106.741 150.311,106.713 150.308,106.686 150.304,106.659 150.298,106.633 150.291,106.608 150.282,106.583 150.272,106.559 150.26,106.536 150.247,106.513 150.233,106.492 150.217,106.471 150.201,106.451 150.183,106.431 150.155,106.404 150.124,106.378 150.091,106.355 150.057,106.333 150.021,106.313 149.984,106.296 149.945,106.281 149.905,106.268 149.865,106.258 149.823,106.25 149.782,106.244 149.74,106.241 149.711,106.241 149.711,105.741 150.211,105.991 150.611,106.741
  region net ISHUNT: 142.398,86.141 142.752,86.495 ccw(c142.238,85.981) 142.471,86.669 142.224,86.422 ccw(c142.912,86.655)
  region net $1N2337: 158.602,128.958 159.102,128.854 ccw(c157.86,128.854) 159.027,129.279 158.677,129.279 ccw(c159.329,128.958)
  region net $1N1798: 163.742,105.492 163.389,105.845 cw(c162.416,106.817) 163.165,105.664 163.561,105.268 cw(c164.714,104.519)
  region net $1N27807: 133.506,117.271 133.534,117.298 133.563,117.321 133.593,117.342 133.624,117.361 133.655,117.378 133.687,117.392 133.719,117.404 133.753,117.415 133.798,117.426 133.844,117.435 133.903,117.443 133.976,117.448 134.139,117.451 134.243,117.451 134.243,117.951 133.743,117.701 133.294,117.484
  region net $1N1788: 146.661,105.079 146.702,105.379 cw(c146.702,108.409) 146.102,105.439 146.084,105.127 ccw(c146.661,108.557)
  region net $1N1788: 150.036,104.426 150.248,104.638 150.237,104.648 150.226,104.657 150.215,104.665 150.195,104.677 150.168,104.692 150.16,104.698 150.153,104.704 150.146,104.71 150.141,104.718 150.136,104.727 150.132,104.738 150.13,104.751 150.128,104.765 149.863,104.5 149.884,104.498 149.907,104.492 149.931,104.485 149.955,104.476 149.979,104.465 150.001,104.453 150.02,104.44
  region net $1N1788: 149.767,105.119 149.555,104.907 149.569,104.891 149.582,104.872 149.594,104.85 149.605,104.826 149.614,104.802 149.621,104.778 149.626,104.755 149.629,104.734 149.894,104.999 149.879,105.001 149.867,105.003 149.856,105.007 149.847,105.012 149.839,105.017 149.833,105.024 149.827,105.031 149.821,105.039 149.806,105.066 149.794,105.086 149.786,105.097 149.777,105.108
  region net $1N2337: 160.038,126.86 160.038,127.36 cw(c160.038,127.768) 159.63,127.735 159.63,126.485 cw(c160.038,126.451)
  region net $1N2337: 157.28,127.36 157.28,126.86 cw(c157.28,125.922) 158.03,126.485 158.03,127.735 cw(c157.28,128.297)

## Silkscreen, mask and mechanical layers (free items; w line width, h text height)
Top Silkscreen Layer:
  text "BFMC POWER BOARD A SAMPLE (FOOTPRINT<0603)" at 84.785,150.113 h3.05
  text "Engine" at 125.775,132.475 h3.05
  text "Bat2" at 144.01,132.229 h3.05
  text "Bat1" at 160.256,132.237 h3.05
  text "BFMC POWER BOARD  V1.0" at 107.889,85.991 h3.05
Mechanical Layer:
  circle w0.025: c99.547,136.879 r1.25
  circle w0.025: c99.564,113.992 r1.25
